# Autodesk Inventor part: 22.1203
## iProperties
Created: 2007-01
Part Number: 22.1203
Material: PVC-U
Document SubType Name: Modeling
Designer: Andy Moles
Density: 1.4 g/cm^3
Description: HOLE CAP M6
Vendor: S
Author: Andy Moles
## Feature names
1. Revolution1
